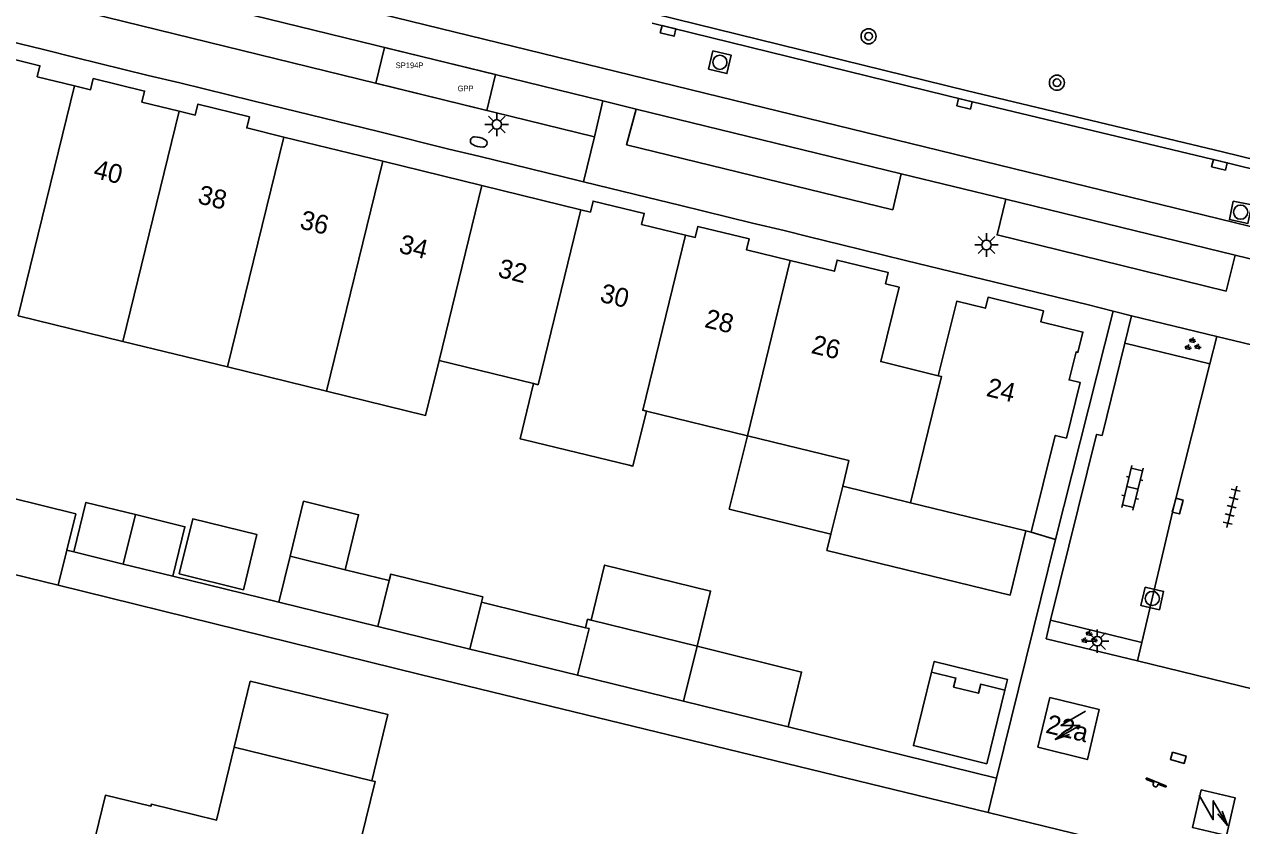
# Model space of a CAD drawing. Extents: x 125000 to 129004, y 397500 to 399008.
# Drawn here: x 126612.3 to 126676.8, y 398245.2 to 398287.6 of the extents above; entities that cross this region are included whole.
import ezdxf

# ---------------------------------------------------------------- set-up
doc = ezdxf.new("R2010")
doc.units = 0
for name, color, linetype in [('bp-anno-kenteken', 7, 'Continuous'), ('bp-grn-parkeervak', 7, 'Continuous'), ('gg-afsc-erfafscheiding', 7, 'Continuous'), ('gg-afsc-hekwerk', 7, 'Continuous'), ('gg-afsc-muur', 7, 'Continuous'), ('gg-anno-huisnummerreeks BGT', 7, 'Continuous'), ('gg-bbg-bijgebouw', 7, 'Continuous'), ('gg-bbg-gedigitaliseerde bebouwing', 7, 'Continuous'), ('gg-bbg-gedigitaliseerde bijgebouw', 7, 'Continuous'), ('gg-bbg-hoofdgebouw', 7, 'Continuous'), ('gg-bbg-lage trafo', 7, 'Continuous'), ('gg-bbg-luifel en loopbrug', 7, 'Continuous'), ('gg-bbg-tussenscheiding', 7, 'Continuous'), ('gg-knt-verharding', 7, 'Continuous'), ('gg-knt-verharding nz', 7, 'Continuous'), ('gt-grn-weggrens', 7, 'Continuous'), ('gt-symb-boom', 7, 'Continuous'), ('gt-symb-brandkraan', 7, 'Continuous'), ('gt-symb-groenvak', 7, 'Continuous'), ('gt-symb-klinker verharding', 7, 'Continuous'), ('gt-symb-kolk', 7, 'Continuous'), ('gt-symb-kolk center center', 7, 'Continuous'), ('gt-symb-lichtmast', 7, 'Continuous'), ('gt-symb-rioolschacht', 7, 'Continuous'), ('gt-symb-speelvoorziening', 7, 'Continuous'), ('gt-symb-tegel verharding', 7, 'Continuous'), ('gt-symb-trafo symbool', 7, 'Continuous'), ('kenmerkpunt gehandicapten parkeerplaats', 7, 'Continuous')]:
    doc.layers.add(name, color=color, linetype=linetype)

# ---------------------------------------------------------------- blocks, each defined once
blk = doc.blocks.new('gt0-HSP')
at = {"layer": 'gt-symb-trafo symbool'}
for points in [[(0.771, 0.746), (-0.529, -0.004), (0.471, -0.004), (-0.829, -0.754)], [(-0.217, -0.24), (-0.829, -0.754), (-0.077, -0.48)]]:
    blk.add_lwpolyline(points, dxfattribs=at)
blk = doc.blocks.new('gt0-SV')
at = {"layer": 'gt-symb-speelvoorziening'}
for p, q in [((-0.477, 0.255), (-0.08, 0.096)), ((0.542, -0.076), (-0.449, 0.324)), ((0.125, 0.014), (0.515, -0.143))]:
    blk.add_line(p, q, dxfattribs=at)
for centre, radius, start, end in [((-0.466, 0.291), 0.0369, 63.6251, 252.66016), ((-0.002, -0.005), 0.128, 127.68665, 8.59861), ((0.531, -0.111), 0.0363, 243.50852, 72.54358)]:
    blk.add_arc(centre, radius, start, end, dxfattribs=at)
blk = doc.blocks.new('gt0-KOLKCC')
at = {"layer": 'gt-symb-kolk center center'}
blk.add_lwpolyline([(-0.375, 0.2), (0.375, 0.2), (0.375, -0.2), (-0.375, -0.2)], close=True, dxfattribs=at)
blk = doc.blocks.new('gt0-LMAST')
at = {"layer": 'gt-symb-lichtmast'}
for p, q in [((-0.182, 0.173), (-0.447, 0.438)), ((-0.005, 0.246), (-0.005, 0.621)), ((0.172, 0.173), (0.437, 0.438)), ((-0.255, -0.004), (-0.63, -0.004)), ((-0.182, -0.181), (-0.447, -0.446)), ((-0.005, -0.254), (-0.005, -0.629)), ((0.437, -0.446), (0.172, -0.181)), ((0.245, -0.004), (0.62, -0.004))]:
    blk.add_line(p, q, dxfattribs=at)
blk.add_circle((-0.005, -0.004), 0.25, dxfattribs=at)
blk = doc.blocks.new('gt0-RS')
at = {"layer": 'gt-symb-rioolschacht'}
blk.add_lwpolyline([(-0.5, -0.5), (0.5, -0.5), (0.5, 0.5), (-0.5, 0.5)], close=True, dxfattribs=at)
blk.add_circle((0, 0), 0.375, dxfattribs=at)
blk = doc.blocks.new('gt0-BOOM')
at = {"layer": 'gt-symb-boom'}
for radius in [0.4, 0.2]:
    blk.add_circle((0, 0), radius, dxfattribs=at)
blk = doc.blocks.new('gt0-KOLK')
at = {"layer": 'gt-symb-kolk'}
blk.add_lwpolyline([(0, 0), (0.375, 0), (0.375, 0.4), (-0.375, 0.4), (-0.375, 0), (0, 0)], dxfattribs=at)
blk = doc.blocks.new('gt0-BR')
at = {"layer": 'gt-symb-brandkraan'}
for centre, radius, start, end in [((-0.244, 0), 0.206, 107.56694, 252.43307), ((0.599, -2.664), 3, 106.89205, 107.56694), ((0, -0.691), 0.938, 73.10799, 106.89205), ((-0.599, -2.664), 3, 72.43309, 73.10799), ((0.244, 0), 0.206, 287.56695, 72.43309), ((0.599, 2.664), 3, 252.43307, 253.10797), ((0, 0.691), 0.938, 253.10797, 286.89206), ((-0.599, 2.664), 3, 286.89206, 287.56695)]:
    blk.add_arc(centre, radius, start, end, dxfattribs=at)
blk = doc.blocks.new('gt0-GRVAK')
at = {"layer": 'gt-symb-groenvak'}
for p, q in [((-0.11, 0.189), (-0.228, 0.24)), ((-0.182, 0.153), (0.088, 0.153)), ((-0.091, 0.211), (-0.156, 0.322)), ((-0.047, 0.214), (-0.047, 0.393)), ((-0.004, 0.211), (0.061, 0.322)), ((0.015, 0.189), (0.133, 0.24)), ((0.262, -0.052), (0.197, 0.059)), ((0.305, -0.049), (0.305, 0.13)), ((0.349, -0.052), (0.414, 0.059)), ((-0.245, -0.228), (-0.363, -0.177)), ((-0.318, -0.264), (-0.047, -0.264)), ((-0.226, -0.206), (-0.291, -0.095)), ((-0.183, -0.203), (-0.183, -0.024)), ((-0.139, -0.206), (-0.074, -0.095)), ((-0.12, -0.228), (-0.002, -0.177)), ((0.243, -0.074), (0.125, -0.023)), ((0.17, -0.11), (0.441, -0.11)), ((0.368, -0.074), (0.486, -0.023))]:
    blk.add_line(p, q, dxfattribs=at)
blk = doc.blocks.new('gt0-TEG1')
at = {"layer": 'gt-symb-tegel verharding'}
for p, q in [((-1.125, 0), (1.125, 0)), ((-0.9, -0.25), (-0.9, 0.25)), ((-0.45, -0.25), (-0.45, 0.25)), ((0, -0.25), (0, 0.25)), ((0.45, -0.25), (0.45, 0.25)), ((0.9, -0.25), (0.9, 0.25))]:
    blk.add_line(p, q, dxfattribs=at)
blk = doc.blocks.new('gt0-KL1')
at = {"layer": 'gt-symb-klinker verharding'}
for p, q in [((-1.15, 0.3), (1.15, 0.3)), ((-1, -0.3), (-1, 0.3)), ((-0.5, 0.3), (-0.5, 0.45)), ((0, -0.3), (0, 0.3)), ((0.5, 0.3), (0.5, 0.45)), ((1, -0.3), (1, 0.3)), ((-1.15, -0.3), (1.15, -0.3)), ((-0.5, -0.45), (-0.5, -0.3)), ((0.5, -0.45), (0.5, -0.3))]:
    blk.add_line(p, q, dxfattribs=at)

msp = doc.modelspace()

# ---------------------------------------------------------------- linework, layer by layer
at = {"layer": 'bp-grn-parkeervak'}
msp.add_lwpolyline([(126637.275, 398284.972), (126636.81, 398283.074), (126630.934, 398284.516), (126631.399, 398286.412), (126637.275, 398284.972)], dxfattribs=at)
at = {"layer": 'gg-afsc-erfafscheiding'}
for p, q in [((126614.946, 398259.702), (126614.578, 398259.793)), ((126625.803, 398257.041), (126620.19, 398258.417)), ((126614.122, 398257.941), (126633.293, 398253.219)), ((126663.793, 398247.727), (126652.757, 398250.44))]:
    msp.add_line(p, q, dxfattribs=at)
at = {"layer": 'gg-afsc-hekwerk'}
for p, q in [((126666.924, 398260.369), (126663.793, 398247.727)), ((126666.924, 398260.369), (126665.631, 398260.745)), ((126633.293, 398253.219), (126663.346, 398245.91)), ((126663.346, 398245.91), (126680.704, 398241.689))]:
    msp.add_line(p, q, dxfattribs=at)
at = {"layer": 'gg-afsc-muur'}
for p, q in [((126609.476, 398287.239), (126613.35, 398286.293)), ((126615.016, 398285.884), (126618.888, 398284.928)), ((126620.557, 398284.532), (126624.424, 398283.579)), ((126626.091, 398283.172), (126629.556, 398282.324)), ((126631.147, 398281.936), (126634.803, 398281.032)), ((126636.397, 398280.648), (126640.054, 398279.753)), ((126641.644, 398279.369), (126641.934, 398279.298)), ((126641.934, 398279.298), (126645.344, 398278.469)), ((126647.004, 398278.061), (126650.884, 398277.113)), ((126652.55, 398276.711), (126653.872, 398276.38)), ((126655.541, 398275.98), (126658.973, 398275.138)), ((126662.021, 398274.398), (126668.6, 398272.801))]:
    msp.add_line(p, q, dxfattribs=at)
at = {"layer": 'gg-bbg-bijgebouw'}
for p, q in [((126614.578, 398259.793), (126614.122, 398257.941)), ((126608.847, 398259.227), (126614.122, 398257.941)), ((126647.943, 398254.713), (126642.333, 398256.092)), ((126638.205, 398254.017), (126635.918, 398254.562)), ((126638.205, 398254.017), (126641.617, 398253.179)), ((126641.617, 398253.179), (126647.227, 398251.8))]:
    msp.add_line(p, q, dxfattribs=at)
for points in [[(126609.771, 398263.018), (126615.052, 398261.718), (126614.578, 398259.793)], [(126642.036, 398255.69), (126642.145, 398256.138), (126642.333, 398256.092)]]:
    msp.add_lwpolyline(points, dxfattribs=at)
at = {"layer": 'gg-bbg-gedigitaliseerde bebouwing'}
msp.add_lwpolyline([(126628.327, 398268.212), (126633.572, 398266.929), (126634.282, 398269.832)], dxfattribs=at)
at = {"layer": 'gg-bbg-gedigitaliseerde bijgebouw'}
for p, q in [((126617.568, 398259.06), (126618.211, 398261.682)), ((126617.568, 398259.06), (126614.946, 398259.702)), ((126625.803, 398257.041), (126626.398, 398259.47)), ((126626.398, 398259.47), (126629.312, 398258.756)), ((126629.312, 398258.756), (126631.643, 398258.184)), ((126631.048, 398255.756), (126625.803, 398257.041)), ((126638.806, 398256.479), (126636.524, 398257.037)), ((126638.806, 398256.479), (126642.036, 398255.69)), ((126635.918, 398254.562), (126631.048, 398255.756)), ((126652.757, 398250.44), (126647.227, 398251.8))]:
    msp.add_line(p, q, dxfattribs=at)
for points in [[(126614.946, 398259.702), (126615.589, 398262.325), (126618.211, 398261.682)], [(126620.529, 398258.54), (126621.244, 398261.453), (126624.643, 398260.619), (126623.928, 398257.705), (126620.529, 398258.54)], [(126636.524, 398257.037), (126636.595, 398257.329), (126631.725, 398258.52), (126631.643, 398258.184)], [(126647.943, 398254.713), (126653.476, 398253.343), (126652.757, 398250.44)], [(126664.24, 398252.378), (126663.277, 398248.489), (126659.394, 398249.451), (126660.357, 398253.34)], [(126660.357, 398253.34), (126661.641, 398253.022), (126661.523, 398252.546), (126662.837, 398252.221), (126662.955, 398252.696), (126664.24, 398252.378)]]:
    msp.add_lwpolyline(points, dxfattribs=at)
at = {"layer": 'gg-bbg-hoofdgebouw'}
for p, q in [((126631.304, 398280.385), (126626.059, 398281.667)), ((126636.549, 398279.102), (126631.304, 398280.385)), ((126641.795, 398277.82), (126636.549, 398279.102)), ((126617.545, 398270.85), (126612.009, 398272.204)), ((126623.082, 398269.495), (126617.545, 398270.85)), ((126628.327, 398268.212), (126623.082, 398269.495)), ((126639.285, 398268.612), (126634.282, 398269.832)), ((126650.605, 398265.852), (126645.258, 398267.157)), ((126644.356, 398264.295), (126638.816, 398265.638)), ((126659.245, 398262.302), (126655.65, 398263.179)), ((126659.245, 398262.302), (126665.34, 398260.816)), ((126665.34, 398260.816), (126665.631, 398260.745)), ((126623.443, 398249.362), (126630.731, 398247.592))]:
    msp.add_line(p, q, dxfattribs=at)
for points in [[(126609.447, 398285.723), (126610.308, 398285.512), (126610.453, 398286.106), (126613.159, 398285.443), (126613.017, 398284.859), (126614.986, 398284.381)], [(126620.525, 398283.036), (126618.552, 398283.521), (126618.693, 398284.104), (126615.98, 398284.758), (126615.838, 398284.174), (126614.986, 398284.381)], [(126626.059, 398281.667), (126624.101, 398282.146), (126624.244, 398282.729), (126621.521, 398283.409), (126621.378, 398282.826), (126620.525, 398283.036)], [(126647.334, 398276.476), (126645.008, 398277.04), (126645.15, 398277.623), (126642.439, 398278.28), (126642.296, 398277.697), (126641.795, 398277.82)], [(126652.874, 398275.132), (126650.566, 398275.692), (126650.707, 398276.275), (126647.987, 398276.935), (126647.845, 398276.352), (126647.334, 398276.476)], [(126660.712, 398269.031), (126657.665, 398269.782), (126658.637, 398273.725), (126657.918, 398273.899), (126658.062, 398274.492), (126655.351, 398275.149), (126655.21, 398274.566), (126652.874, 398275.132)], [(126665.631, 398260.745), (126666.9, 398265.875), (126667.494, 398265.728), (126668.222, 398268.668), (126667.638, 398268.813), (126668.004, 398270.292), (126668.101, 398270.268), (126668.366, 398271.339), (126666.135, 398271.885), (126666.278, 398272.467), (126663.349, 398273.183), (126663.207, 398272.601), (126661.684, 398272.974), (126660.712, 398269.031)], [(126638.816, 398265.638), (126638.577, 398265.696), (126639.285, 398268.612)], [(126645.258, 398267.157), (126644.548, 398264.248), (126644.356, 398264.295)], [(126655.65, 398263.179), (126655.981, 398264.539), (126650.605, 398265.852)], [(126665.985, 398249.372), (126666.62, 398251.992), (126669.221, 398251.362), (126668.605, 398248.712), (126665.985, 398249.372)], [(126616.379, 398235.365), (126617.25, 398238.904), (126616.674, 398239.046), (126617.249, 398241.382), (126615.411, 398241.835), (126616.621, 398246.82), (126619.031, 398246.235), (126619.057, 398246.342), (126622.507, 398245.504), (126623.443, 398249.362)], [(126630.731, 398247.592), (126630.896, 398247.552), (126628.227, 398236.626), (126624.698, 398237.471), (126623.783, 398233.577), (126623.676, 398233.602), (126623.401, 398232.434), (126619.698, 398233.305), (126619.985, 398234.485), (126616.379, 398235.365)]]:
    msp.add_lwpolyline(points, dxfattribs=at)
at = {"layer": 'gg-bbg-lage trafo'}
msp.add_lwpolyline([(126674.632, 398247.106), (126676.422, 398246.693), (126675.961, 398244.699), (126674.172, 398245.113), (126674.632, 398247.106)], dxfattribs=at)
at = {"layer": 'gg-bbg-luifel en loopbrug'}
for p, q in [((126655.027, 398260.646), (126655.65, 398263.179)), ((126620.19, 398258.417), (126617.568, 398259.06))]:
    msp.add_line(p, q, dxfattribs=at)
for points in [[(126650.605, 398265.852), (126649.65, 398261.968), (126655.027, 398260.646)], [(126626.398, 398259.47), (126627.113, 398262.383), (126630.027, 398261.668), (126629.312, 398258.756)], [(126618.211, 398261.682), (126620.833, 398261.039), (126620.19, 398258.417)], [(126665.34, 398260.816), (126664.51, 398257.416), (126654.816, 398259.779), (126655.027, 398260.646)], [(126642.333, 398256.092), (126643.049, 398259.005), (126648.659, 398257.626), (126647.943, 398254.713)], [(126664.24, 398252.378), (126664.381, 398252.947), (126660.498, 398253.909), (126660.357, 398253.34)], [(126623.443, 398249.362), (126624.293, 398252.86), (126631.581, 398251.09), (126630.731, 398247.592)]]:
    msp.add_lwpolyline(points, dxfattribs=at)
at = {"layer": 'gg-bbg-tussenscheiding'}
for p, q in [((126612.009, 398272.204), (126614.986, 398284.381)), ((126617.545, 398270.85), (126620.525, 398283.036)), ((126626.059, 398281.667), (126623.082, 398269.495)), ((126628.327, 398268.212), (126631.304, 398280.385)), ((126634.282, 398269.832), (126636.549, 398279.102)), ((126652.874, 398275.132), (126650.605, 398265.852)), ((126631.643, 398258.184), (126631.048, 398255.756)), ((126635.918, 398254.562), (126636.524, 398257.037)), ((126647.227, 398251.8), (126647.943, 398254.713))]:
    msp.add_line(p, q, dxfattribs=at)
for points in [[(126639.285, 398268.612), (126639.529, 398268.553), (126641.795, 398277.82)], [(126645.258, 398267.157), (126645.067, 398267.204), (126647.334, 398276.476)], [(126660.712, 398269.031), (126660.887, 398268.988), (126659.245, 398262.302)], [(126641.617, 398253.179), (126642.223, 398255.644), (126642.036, 398255.69)]]:
    msp.add_lwpolyline(points, dxfattribs=at)
at = {"layer": 'gg-knt-verharding'}
for p, q in [((126562.672, 398303.26), (126642.957, 398283.579)), ((126562.214, 398301.381), (126642.512, 398281.675)), ((126613.35, 398286.293), (126615.016, 398285.884)), ((126618.888, 398284.928), (126620.557, 398284.532)), ((126624.424, 398283.579), (126626.091, 398283.172)), ((126642.512, 398281.675), (126642.957, 398283.579)), ((126642.957, 398283.579), (126644.725, 398283.144)), ((126644.725, 398283.144), (126658.746, 398279.719)), ((126629.556, 398282.324), (126631.147, 398281.936)), ((126634.803, 398281.032), (126636.397, 398280.648)), ((126640.054, 398279.753), (126641.644, 398279.369)), ((126658.746, 398279.719), (126664.282, 398278.376)), ((126645.344, 398278.469), (126647.004, 398278.061)), ((126664.282, 398278.376), (126676.422, 398275.41)), ((126650.884, 398277.113), (126652.55, 398276.711)), ((126653.872, 398276.38), (126655.541, 398275.98)), ((126676.422, 398275.41), (126682.851, 398273.834)), ((126658.973, 398275.138), (126662.021, 398274.398)), ((126668.6, 398272.801), (126669.973, 398272.453)), ((126669.973, 398272.453), (126666.924, 398260.369)), ((126670.586, 398270.751), (126670.938, 398272.196)), ((126670.938, 398272.196), (126675.455, 398271.105)), ((126675.09, 398269.659), (126670.586, 398270.751)), ((126675.455, 398271.105), (126675.09, 398269.659)), ((126671.486, 398254.914), (126666.65, 398256.083)), ((126671.486, 398254.914), (126671.248, 398253.934))]:
    msp.add_line(p, q, dxfattribs=at)
for points in [[(126752.63, 398262.103), (126710.709, 398272.342), (126692.936, 398276.664), (126675.757, 398280.878), (126662.261, 398284.112), (126645.683, 398288.185)], [(126735.874, 398265.675), (126710.591, 398271.856), (126692.817, 398276.178), (126675.639, 398280.392), (126662.143, 398283.626), (126645.565, 398287.699)], [(126644.725, 398283.144), (126644.215, 398281.261), (126658.3, 398277.82), (126658.746, 398279.719)], [(126664.282, 398278.376), (126663.82, 398276.487), (126675.947, 398273.515), (126676.422, 398275.41)], [(126666.65, 398256.083), (126669.087, 398265.927), (126669.379, 398265.871), (126670.586, 398270.751)], [(126675.09, 398269.659), (126673.19, 398262.179), (126671.486, 398254.914)], [(126671.248, 398253.934), (126666.426, 398255.108), (126666.65, 398256.083)]]:
    msp.add_lwpolyline(points, dxfattribs=at)
at = {"layer": 'gg-knt-verharding nz'}
msp.add_lwpolyline([(126735.152, 398262.709), (126682.577, 398275.631), (126565.798, 398304.172), (126519.837, 398315.436)], dxfattribs=at)
at = {"layer": 'gt-grn-weggrens'}
for p, q in [((126642.512, 398281.675), (126641.934, 398279.298)), ((126670.938, 398272.196), (126669.973, 398272.453)), ((126681.618, 398269.614), (126675.455, 398271.105)), ((126677.464, 398252.414), (126671.248, 398253.934)), ((126663.346, 398245.91), (126663.793, 398247.727))]:
    msp.add_line(p, q, dxfattribs=at)

# ---------------------------------------------------------------- block references
at = {"layer": 'gt-symb-boom'}
for p in [(126657.02, 398286.999), (126666.99, 398284.542)]:
    msp.add_blockref('gt0-BOOM', p, dxfattribs=at)
at = {"layer": 'gt-symb-brandkraan', "rotation": -14.064036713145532}
msp.add_blockref('gt0-BR', (126636.383, 398281.405), dxfattribs=at)
at = {"layer": 'gt-symb-groenvak'}
for p, rotation in [((126674.154, 398270.66), -13.702889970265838), ((126668.681, 398255.147), -13.716469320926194)]:
    msp.add_blockref('gt0-GRVAK', p, dxfattribs=dict(at, rotation=rotation))
at = {"layer": 'gt-symb-klinker verharding', "rotation": 76.35276166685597}
msp.add_blockref('gt0-KL1', (126670.985, 398263.096), dxfattribs=at)
at = {"layer": 'gt-symb-kolk'}
for p, rotation in [((126646.453, 398287.478), 166.22785456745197), ((126662.143, 398283.626), 166.51987378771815), ((126675.639, 398280.392), 166.22785456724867), ((126673.19, 398262.179), -104.24474247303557)]:
    msp.add_blockref('gt0-KOLK', p, dxfattribs=dict(at, rotation=rotation))
at = {"layer": 'gt-symb-kolk center center', "rotation": -16.512958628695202}
msp.add_blockref('gt0-KOLKCC', (126673.416, 398248.806), dxfattribs=at)
at = {"layer": 'gt-symb-lichtmast'}
for p in [(126637.343, 398282.342), (126663.267, 398275.956), (126669.127, 398254.984)]:
    msp.add_blockref('gt0-LMAST', p, dxfattribs=at)
at = {"layer": 'gt-symb-rioolschacht'}
for p, rotation in [((126649.151, 398285.626), -13.243802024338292), ((126676.714, 398277.689), -101.71452521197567), ((126672.04, 398257.239), -103.17492660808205)]:
    msp.add_blockref('gt0-RS', p, dxfattribs=dict(at, rotation=rotation))
at = {"layer": 'gt-symb-speelvoorziening'}
msp.add_blockref('gt0-SV', (126672.211, 398247.402), dxfattribs=at)
at = {"layer": 'gt-symb-tegel verharding', "rotation": 76.33923320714}
msp.add_blockref('gt0-TEG1', (126676.243, 398262.098), dxfattribs=at)
at = {"layer": 'gt-symb-trafo symbool'}
msp.add_blockref('gt0-HSP', (126667.733, 398250.519), dxfattribs=at)
at = {"layer": 'gt-symb-trafo symbool', "rotation": 90}
msp.add_blockref('gt0-HSP', (126675.261, 398246.056), dxfattribs=at)

# ---------------------------------------------------------------- texts
at = {"layer": 'bp-anno-kenteken'}
msp.add_text('SP194P', height=0.3, dxfattribs=at).set_placement((126631.988, 398285.314))
at = {"layer": 'gg-anno-huisnummerreeks BGT'}
for s, rotation, p in [('40', 346.4, (126615.939, 398279.518)), ('38', 346.1, (126621.457, 398278.171)), ('36', 346.3, (126626.859, 398276.838)), ('34', 346.2, (126632.104, 398275.557)), ('32', 346.3, (126637.35, 398274.273)), ('30', 346.4, (126642.748, 398272.958)), ('28', 346.4, (126648.288, 398271.614)), ('26', 346.3, (126653.933, 398270.241)), ('24', 346.3, (126663.2, 398267.969)), ('22a', 346.4, (126666.349, 398250.143))]:
    msp.add_text(s, height=1, rotation=rotation, dxfattribs=at).set_placement(p)
at = {"layer": 'kenmerkpunt gehandicapten parkeerplaats'}
msp.add_text('GPP', height=0.3, dxfattribs=at).set_placement((126635.263, 398284.087))

doc.saveas('drawing.dxf')
